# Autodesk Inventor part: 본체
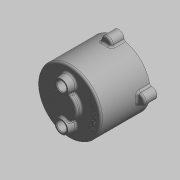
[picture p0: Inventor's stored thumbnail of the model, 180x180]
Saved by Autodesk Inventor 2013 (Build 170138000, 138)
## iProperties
Created: 2015-11
Part Number: 본체
Document SubType Name: 모델링
Designer: mdu
Material: 알루미늄 6061
Density: 2.71 g/cm^3
Mass: 464.621 g
Surface Area: 669.592 cm^2
Volume: 171.447 cm^3
변환 표준: STEP AP214IS
파일 이름: C:\Users\SeoGD\Desktop\?쒗뿕\紐몄껜.stp
전처리기: Build: 253, Release: 2010 SP1 - Date: Wed 07/29/2009
전송 단위: 밀리미터
불확실성: 0.01
Author: mdu
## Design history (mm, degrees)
sketch "스케치2"
  geometry: C1 r 50 at (0, 0); 1 further point
  constraints: 1 centre point, 1 coincident
  dimensions: "d9" = 100 diameter of C1
extrude "돌출2" new body sketch "스케치2" distance "d10" = 78.5; taper "d11" = 0 deg
feature "쉘1" dims "d12" = 5
sketch "스케치3" dims "d13" = 55
  geometry: C1 r 7.5 at (0, 27.5); C2 r 12.5 at (0, 27.5); 2 further points
  constraints: 2 centre point, 2 coincident, 2 vertical alignment, 2 other
  dimensions: "d14" = 15 diameter of C1; "d15" = 25 diameter of C2
extrude "돌출3" join sketch "스케치3" distance "d16" = 12; taper "d17" = -10 deg
hole "구멍2" diameter "d20" = 15; stored, may be unused: countersink angle "d24" = 90 deg, drill point angle "d26" = 118 deg; dims "d18" = 10, "d19" = 10, "d21" = 6, "d22" = 4, "d23" = 2, "d25" = 15
chamfer "모따기1" distance "d27" = 1; stored, may be unused: second distance "d28" = 2, angle "d29" = 45 deg
sketch "스케치4"
  geometry: L1 (0, 0)-(0, 86.5); L2 (0, 68.5)-(13.16, 68.5); L3 (-45, 73.5)-(45, 73.5) reference; L4 (-50, 78.5)-(50, 78.5) reference; L5 (13.16, 68.5)-(14.5, 73.5); L6 (20, 78.5)-(20, 86.5); L7 (20, 86.5)-(0, 86.5); L8 (20, 78.5)-(14.5, 73.5)
  constraints: 12 end point, 3 point on line, 2 perpendicular, 1 vertical
  dimensions: "d34" = 40 diameter of L6 L1; "d35" = 105 deg angle of L5 L3; "d36" = 5 distance between parallel lines of L2 L3; "d37" = 8 distance between parallel lines of L7 L4; "d51" = 29 diameter of L5.end L1
revolve "회전1" sketch "스케치4" stored, may be unused: angle "d38" = 90 deg
hole "구멍3" diameter "d41" = 15; stored, may be unused: countersink angle "d45" = 90 deg, drill point angle "d47" = 0 deg; dims "d39" = 10, "d40" = 10, "d42" = 6, "d43" = 22, "d44" = 13, "d46" = 15
chamfer "모따기2" distance "d48" = 1; stored, may be unused: second distance "d49" = 2, angle "d50" = 45 deg
fillet "모깎기1" dims "d52" = 3
fillet "모깎기2" dims "d53" = 3, "d72" = 0.2
sketch "스케치5"
  geometry: A1 r 50 centre (0, 0) between (50, 0) and (-8.074, 49.344) reference; A2 r 8.5 centre (0, 52) between (8.074, 49.344) and (-8.074, 49.344); 1 further point
  constraints: 5 point on circle, 1 centre point, 1 horizontal alignment
  dimensions: "d54" = 90 deg dimension on point (0, 0) A2.centre A1.start; "d55" = 52 distance of A2.centre point (0, 0); "d56" = 17 diameter of A2
extrude "돌출4" join sketch "스케치5" distance "d57" = 20; taper "d58" = 0 deg
fillet "모깎기3" dims "d59" = 3
hole "구멍4" diameter "d62" = 4.134; stored, may be unused: countersink angle "d66" = 90 deg, drill point angle "d68" = 118 deg; dims "d60" = 10, "d61" = 10, "d63" = 12, "d64" = 22, "d65" = 13, "d67" = 15
sketch "스케치6"
  geometry: C1 r 47 at (0, 0) reference; C2 r 42.5 at (0, 0); 1 further point
  constraints: 1 centre point, 1 coincident, 1 other
  dimensions: "d73" = 85 diameter of C2
feature "엠보싱1" sketch "스케치6" dims "d74" = 0.5, "d75" = 0
node "솔리드1"
node "솔리드 본체"
node "곡면 본체"
pattern_circular "원형 패턴1" dims "d31" = 360 deg
pattern_circular "원형 패턴2" dims "d70" = 360 deg
node "솔리드2"
